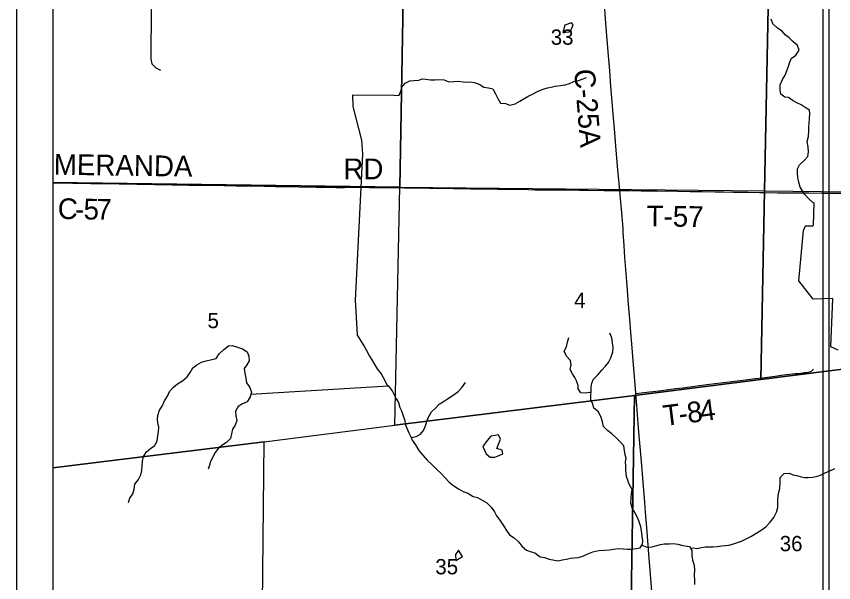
# Model space of a CAD drawing. Extents: x 0 to 1391, y -24 to 440.
# Drawn here: x 490 to 534.79, y 381.91 to 412.96 of the extents above; entities that cross this region are included whole.
import ezdxf

# ---------------------------------------------------------------- set-up
doc = ezdxf.new("R2010")
doc.units = 0
for name, color, linetype in [('GM_X_County_Road', 7, 'Continuous'), ('GM_X_County_Road_Text', 7, 'Continuous'), ('GM_X_Interstate_Route', 7, 'Continuous'), ('GM_X_Minor_Lake', 7, 'Continuous'), ('GM_X_Minor_River', 7, 'Continuous'), ('GM_X_Section', 7, 'Continuous'), ('GM_X_Section_Text', 7, 'Continuous'), ('GM_X_Township', 7, 'Continuous'), ('GM_X_Township_Road', 7, 'Continuous'), ('GM_X_Township_Road_Text', 7, 'Continuous'), ('SH_Data', 7, 'Continuous')]:
    doc.layers.add(name, color=color, linetype=linetype)

msp = doc.modelspace()

# ---------------------------------------------------------------- linework, layer by layer
at = {"layer": 'GM_X_County_Road'}
for points in [[(522.968, 404.52), (522.85, 405.863), (522.775, 406.8), (522.719, 407.384), (522.627, 408.487), (522.583, 409.107), (522.516, 409.987), (522.465, 410.594), (522.354, 411.895), (522.286, 412.812), (522.222, 413.633)], [(523.078, 403.405), (522.983, 404.358), (522.968, 404.52)], [(492, 403.821), (493.098, 403.801), (494.08, 403.789), (495.634, 403.765), (496.603, 403.751), (498.566, 403.719), (499.449, 403.706), (500.17, 403.7), (501.375, 403.677), (502.033, 403.671), (502.605, 403.663), (503.04, 403.657), (503.599, 403.647), (504.208, 403.635), (504.693, 403.631), (505.5, 403.606), (506.444, 403.588), (506.954, 403.585), (507.501, 403.579), (507.973, 403.578), (508.756, 403.581), (509.352, 403.58), (509.937, 403.575), (510.409, 403.569), (511.278, 403.561), (511.925, 403.55), (512.657, 403.536), (513.95, 403.522), (514.546, 403.51), (514.894, 403.504), (515.764, 403.495), (516.373, 403.488), (517.106, 403.481), (517.392, 403.477), (518.063, 403.46), (518.436, 403.45), (520.089, 403.44), (520.859, 403.431), (521.294, 403.426), (522.189, 403.411), (523.078, 403.405)], [(523.26, 401.112), (523.247, 401.319), (523.197, 401.989), (523.114, 402.969), (523.078, 403.405)], [(523.947, 392.283), (523.923, 392.552), (523.821, 393.853), (523.73, 394.993), (523.679, 395.629), (523.639, 396.132), (523.555, 397.173), (523.457, 398.424), (523.349, 399.73), (523.307, 400.388), (523.26, 401.112)], [(525.306, 375.36), (525.265, 375.917), (525.169, 377.156), (524.994, 379.348), (524.898, 380.487), (524.731, 382.594), (524.682, 383.226), (524.546, 384.923), (524.496, 385.53), (524.433, 386.31), (524.345, 387.425), (524.25, 388.552), (524.156, 389.753), (524.084, 390.608), (524.005, 391.636), (523.947, 392.283)]]:
    msp.add_lwpolyline(points, dxfattribs=at)
at = {"layer": 'GM_X_Interstate_Route'}
for points in [[(534.216, 381.071), (534.213, 382.737), (534.211, 383.855), (534.212, 384.936), (534.211, 386.54), (534.212, 388.105), (534.215, 390.206), (534.213, 391.175), (534.214, 392.666), (534.212, 394.307), (534.212, 396.109), (534.209, 397.861), (534.211, 398.321), (534.216, 399.303), (534.216, 400.098), (534.212, 401.142), (534.211, 402.136), (534.215, 403.266), (534.215, 403.4), (534.214, 403.603), (534.218, 404.858), (534.213, 406.598), (534.213, 407.219), (534.218, 408.301), (534.216, 409.444), (534.219, 411.097), (534.219, 412.526), (534.215, 414.39)], [(534.547, 380.674), (534.551, 382.041), (534.55, 383.184), (534.551, 383.495), (534.546, 385.346), (534.546, 386.987), (534.544, 387.472), (534.546, 388.652), (534.548, 389.709), (534.542, 392.02), (534.543, 392.94), (534.544, 394.494), (534.547, 395.91), (534.546, 396.78), (534.544, 397.924), (534.542, 399.067), (534.541, 399.8), (534.539, 400.173), (534.542, 402.273), (534.546, 403.263), (534.547, 403.4), (534.545, 404.784), (534.542, 406.188), (534.546, 406.847), (534.546, 406.959), (534.546, 407.257), (534.546, 407.58), (534.543, 408.4), (534.546, 408.972), (534.547, 409.233), (534.546, 409.755), (534.544, 410.501), (534.542, 411.893), (534.543, 412.551), (534.546, 413.496)]]:
    msp.add_lwpolyline(points, dxfattribs=at)
at = {"layer": 'GM_X_Minor_Lake'}
msp.add_line((514.063, 383.449), (514.087, 383.123), dxfattribs=at)
for points in [[(520.379, 412.172), (520.505, 412.496), (520.423, 412.604), (520.066, 412.473)], [(520.066, 412.473), (519.945, 412.071), (520.272, 412.105), (520.379, 412.172)], [(516.332, 389.263), (516.539, 389.768), (516.422, 390.02), (516.231, 389.971), (515.995, 389.93), (515.793, 389.7), (515.567, 389.379)], [(515.567, 389.379), (515.742, 388.966), (515.974, 388.779), (516.218, 388.782), (516.409, 388.854), (516.654, 388.978), (516.627, 389.168), (516.332, 389.263)], [(514.447, 383.348), (514.234, 383.68), (514.063, 383.449)], [(514.087, 383.123), (514.447, 383.348)]]:
    msp.add_lwpolyline(points, dxfattribs=at)
at = {"layer": 'GM_X_Minor_River'}
msp.add_line((502.85, 392.235), (510.373, 392.692), dxfattribs=at)
for points in [[(497.769, 417.033), (497.745, 414.02), (497.395, 413.403), (497.366, 410.61)], [(533.725, 402.722), (533.65, 402.754), (533.424, 402.946), (533.208, 403.192), (533.074, 403.384), (532.962, 403.582), (532.875, 403.857), (532.818, 404.115), (532.806, 404.351), (532.809, 404.586), (532.925, 404.82), (533.171, 405.044), (533.379, 405.276), (533.405, 405.534), (533.386, 405.8), (533.337, 406.089), (533.409, 406.361), (533.421, 406.687), (533.431, 406.884), (533.441, 407.104), (533.467, 407.354), (533.478, 407.612), (533.466, 407.802), (533.225, 407.949), (533.007, 408.112), (532.773, 408.206), (532.562, 408.315), (532.306, 408.508), (532.117, 408.518), (531.899, 408.688), (531.856, 408.924), (531.852, 409.205), (531.985, 409.484), (532.132, 409.732), (532.227, 409.966), (532.29, 410.17), (532.361, 410.389), (532.463, 410.638), (532.724, 410.832), (532.902, 411.095), (532.814, 411.354), (532.536, 411.586), (532.342, 411.778), (532.139, 411.948), (531.974, 412.14), (531.711, 412.31), (531.464, 412.541), (531.361, 412.808)], [(497.366, 410.61), (497.416, 410.344), (497.648, 410.136), (497.905, 410.012)], [(510.695, 408.608), (510.984, 408.627), (511.07, 408.854), (511.134, 409.081), (511.303, 409.291), (511.563, 409.424), (511.791, 409.444), (512.049, 409.456), (512.24, 409.529), (512.437, 409.504), (512.694, 409.471), (512.937, 409.475), (513.188, 409.487), (513.438, 409.476), (513.695, 409.359), (513.96, 409.379), (514.219, 409.398), (514.484, 409.357), (514.689, 409.354), (514.894, 409.367), (515.09, 409.319), (515.355, 409.232), (515.618, 409.077), (515.868, 409.043), (516.103, 408.972), (516.266, 408.712), (516.377, 408.445), (516.525, 408.2), (516.798, 408.182), (517.047, 408.08), (517.329, 408.167), (517.589, 408.3), (517.857, 408.464), (518.086, 408.597), (518.284, 408.693), (518.529, 408.819), (518.727, 408.908), (518.918, 408.989), (519.116, 409.039), (519.306, 409.075), (519.52, 409.125), (519.816, 409.167), (520.075, 409.209), (520.311, 409.282), (520.555, 409.377), (520.806, 409.442), (521.058, 409.53), (521.248, 409.603)], [(510.695, 408.608), (508.426, 408.629), (508.441, 408.021), (508.918, 406.164), (508.968, 405.397), (508.56, 397.389), (508.679, 395.51)], [(534.643, 394.845), (534.749, 397.48), (533.664, 397.457), (532.872, 398.454), (533.136, 401.205), (533.238, 401.462), (533.625, 401.464), (533.679, 401.509), (533.725, 402.714)], [(510.413, 392.657), (510.315, 392.742), (510.227, 392.932), (510.123, 393.139), (509.989, 393.376), (509.794, 393.621), (509.623, 393.904), (509.504, 394.125), (509.333, 394.386), (509.184, 394.653), (509.058, 394.898), (508.679, 395.51)], [(522.625, 395.328), (522.515, 395.58)], [(511.64, 389.865), (511.684, 389.72), (511.87, 389.46), (512.064, 389.153), (512.266, 388.908), (512.521, 388.631), (512.769, 388.385), (513.047, 388.108), (513.257, 387.915), (513.505, 387.661), (513.723, 387.415), (513.971, 387.214), (514.228, 387.051), (514.484, 386.903), (514.749, 386.808), (515.028, 386.63), (515.271, 386.58), (515.528, 386.425), (515.777, 386.277), (516.017, 386.053), (516.204, 385.793), (516.315, 385.571), (516.503, 385.341), (516.674, 385.066), (516.815, 384.813), (517.032, 384.522), (517.281, 384.359), (517.522, 384.143), (517.716, 383.897), (517.964, 383.689), (518.161, 383.61), (518.419, 383.538), (518.698, 383.329), (518.94, 383.279), (519.19, 383.192), (519.684, 383.108), (519.912, 383.15), (520.156, 383.192), (520.37, 383.241), (520.56, 383.261), (520.781, 383.295), (521.041, 383.359), (521.316, 383.491), (521.584, 383.593), (521.919, 383.664), (522.239, 383.689), (522.506, 383.707), (522.727, 383.734), (522.986, 383.775), (523.259, 383.763), (523.495, 383.744), (523.708, 383.741), (523.982, 383.774), (524.188, 383.824), (524.32, 384.026), (524.323, 384.216), (524.295, 384.451), (524.254, 384.763), (524.226, 384.975), (524.123, 385.25), (524.065, 385.448), (523.916, 385.723), (523.752, 386.006), (523.68, 386.28), (523.691, 386.545), (523.717, 386.794), (523.743, 387.021), (523.572, 387.335), (523.513, 387.525), (523.44, 387.723), (523.399, 388.057), (523.394, 388.307), (523.382, 388.527), (523.415, 388.724), (523.364, 388.914), (523.322, 389.157), (523.287, 389.408), (523.069, 389.654), (522.844, 389.869), (522.633, 390.062), (522.4, 390.255), (522.182, 390.471), (522.125, 390.715), (522.052, 390.958), (521.896, 391.264), (521.655, 391.48), (521.59, 391.716), (521.486, 391.907), (521.474, 392.165), (521.508, 392.429), (521.503, 392.619), (521.544, 392.853), (521.63, 393.056), (521.869, 393.295), (522.078, 393.557), (522.294, 393.78), (522.456, 393.982), (522.581, 394.23), (522.692, 394.562), (522.71, 394.797), (522.625, 395.328)], [(521.499, 392.364), (521.423, 392.325), (521.187, 392.29), (520.928, 392.317), (520.779, 392.532), (520.781, 392.721), (520.701, 392.965), (520.604, 393.156), (520.478, 393.347), (520.344, 393.592), (520.4, 393.841), (520.366, 394.092), (520.14, 394.33), (520.022, 394.597), (520.155, 394.838), (520.211, 395.094), (520.268, 395.351)], [(496.153, 386.299), (496.225, 386.533), (496.38, 386.773), (496.46, 387.03), (496.486, 387.302), (496.695, 387.556), (496.82, 387.812), (496.868, 388.061), (496.887, 388.311), (496.913, 388.568), (496.977, 388.825), (497.14, 389.087), (497.379, 389.273), (497.57, 389.414), (497.726, 389.669), (497.76, 389.979), (497.793, 390.183), (497.812, 390.433), (497.754, 390.661), (497.734, 390.874), (497.759, 391.07), (497.839, 391.365), (497.986, 391.582), (498.112, 391.883), (498.275, 392.123), (498.4, 392.379), (498.608, 392.633), (498.839, 392.804), (499.107, 392.966), (499.353, 393.182), (499.531, 393.422), (499.672, 393.677), (499.894, 393.856), (500.147, 393.996), (500.407, 394.075), (500.704, 394.139), (500.949, 394.203), (501.112, 394.458), (501.366, 394.689), (501.627, 394.89), (501.832, 394.902), (502.113, 394.822), (502.401, 394.727), (502.657, 394.556), (502.738, 394.327), (502.765, 394.069), (502.633, 393.844), (502.478, 393.649), (502.513, 393.391), (502.57, 393.125), (502.62, 392.859), (502.791, 392.599), (502.887, 392.355), (502.808, 392.099), (502.652, 391.828), (502.392, 391.704), (502.154, 391.571), (502.014, 391.315), (502.034, 391.057), (502.091, 390.791), (501.997, 390.55), (501.842, 390.325), (501.785, 390.069), (501.744, 389.804), (501.52, 389.595), (501.321, 389.455), (501.067, 389.254), (500.858, 388.984), (500.749, 388.751), (500.64, 388.548), (500.584, 388.352), (500.513, 388.133)], [(535.031, 394.649), (534.643, 394.845)], [(510.413, 392.657), (510.6, 392.427), (510.696, 392.198), (510.808, 391.984), (510.934, 391.777), (511.022, 391.511), (511.103, 391.32), (511.199, 391.053), (511.272, 390.848), (511.322, 390.559), (511.403, 390.368), (511.514, 390.117), (511.64, 389.865), (511.907, 389.914), (512.144, 390.046), (512.307, 390.256), (512.416, 390.512), (512.488, 390.768), (512.613, 391.024), (512.753, 391.279), (512.946, 391.451), (513.169, 391.69), (513.415, 391.845), (513.629, 391.978), (513.929, 392.186), (514.205, 392.393), (514.436, 392.625), (514.622, 392.887)], [(526.939, 383.805), (527.094, 383.815), (527.291, 383.781), (527.543, 383.83), (527.756, 383.872), (527.969, 383.876), (528.182, 383.873), (528.411, 383.884), (528.662, 383.918), (528.853, 383.938), (529.051, 383.965), (529.249, 384.022), (529.524, 384.109), (529.73, 384.181), (529.991, 384.306), (530.259, 384.445), (530.573, 384.645), (530.818, 384.785), (531.079, 384.97), (531.311, 385.224), (531.512, 385.486), (531.66, 385.771), (531.724, 386.028), (531.728, 386.27), (531.738, 386.467), (531.772, 386.792), (531.844, 387.072), (531.849, 387.412), (531.86, 387.67), (532.083, 387.893), (532.342, 387.904), (532.554, 387.825), (532.766, 387.776), (533.001, 387.704), (533.206, 387.671), (533.396, 387.667), (533.64, 387.694), (533.831, 387.721), (534.075, 387.808), (534.328, 387.933), (534.588, 388.042), (534.848, 388.159)], [(524.282, 383.969), (524.554, 383.856), (524.835, 383.874), (525.095, 383.946), (525.293, 383.996), (525.492, 384.03), (525.796, 384.041), (525.986, 384.045), (526.244, 384.018), (526.449, 383.969), (526.639, 383.921), (526.897, 383.886), (527.008, 383.672), (527.02, 383.399), (527.055, 383.134), (527.142, 382.859), (527.162, 382.586), (527.151, 382.321), (527.162, 382.048), (527.167, 381.798)]]:
    msp.add_lwpolyline(points, dxfattribs=at)
at = {"layer": 'GM_X_Section'}
for p, q in [((492, 403.851), (492, 388.207)), ((492, 388.207), (492, 375.413))]:
    msp.add_line(p, q, dxfattribs=at)
for points in [[(511.262, 418), (492, 418), (492, 403.851)], [(492, 403.851), (511.009, 403.582), (511.262, 418)], [(511.262, 418), (511.009, 403.582), (531.004, 403.382), (531.299, 418)], [(531.299, 418), (531.004, 403.382), (551.127, 403.143), (551.455, 418)], [(492, 388.207), (503.573, 389.632), (510.734, 390.543), (511.009, 403.582), (492, 403.851)], [(492, 375.413), (503.435, 375.392), (503.573, 389.632), (492, 388.207)]]:
    msp.add_lwpolyline(points, dxfattribs=at)
for points in [[(511.009, 403.582), (531.004, 403.382), (530.802, 393.045), (523.87, 392.175), (510.734, 390.543)], [(531.004, 403.382), (551.127, 403.143), (550.964, 395.616), (548.844, 395.312), (543.962, 394.707), (530.802, 393.045)], [(530.802, 393.045), (543.962, 394.707), (543.747, 375.22), (523.606, 375.279), (523.87, 392.175)], [(523.87, 392.175), (523.606, 375.279), (503.957, 375.36), (503.435, 375.392), (503.573, 389.632), (510.734, 390.543)]]:
    msp.add_lwpolyline(points, close=True, dxfattribs=at)
at = {"layer": 'GM_X_Township'}
msp.add_lwpolyline([(563.833, 373.178), (563.849, 374.981), (563.918, 383.057), (564.071, 397.264), (576.025, 398.776), (588.961, 400.394), (591.398, 400.66), (591.42, 402.56), (591.526, 412.457), (591.623, 418), (492, 418), (492, 315.227)], dxfattribs=at)
at = {"layer": 'GM_X_Township_Road'}
for points in [[(523.078, 403.405), (523.616, 403.398), (524.237, 403.391), (525.033, 403.396), (525.12, 403.396), (526.21, 403.377), (526.918, 403.36), (527.589, 403.352), (528.297, 403.339), (528.744, 403.328), (529.303, 403.321), (530.111, 403.309), (530.732, 403.299), (530.959, 403.296)], [(530.959, 403.296), (531.726, 403.288), (532.186, 403.283), (532.683, 403.284), (533.428, 403.275), (534.215, 403.266), (534.546, 403.263), (535.23, 403.258), (535.801, 403.25), (536.434, 403.238), (536.944, 403.234), (537.28, 403.231)], [(523.947, 392.283), (524.105, 392.297), (524.24, 392.309), (524.696, 392.364), (525.226, 392.43), (526.113, 392.543), (526.532, 392.597), (527.838, 392.762), (528.294, 392.818), (529.81, 393.007), (530.5, 393.094), (530.882, 393.141), (531.584, 393.23), (531.917, 393.274), (532.682, 393.366), (532.806, 393.381), (533.115, 393.418), (533.171, 393.425)], [(533.171, 393.425), (533.275, 393.437), (533.372, 393.452), (533.444, 393.467), (533.537, 393.491), (533.569, 393.504), (533.606, 393.53), (533.631, 393.552), (533.656, 393.581), (533.679, 393.609)]]:
    msp.add_lwpolyline(points, dxfattribs=at)
at = {"layer": 'SH_Data'}
for p, q in [((490, 420), (490, 280)), ((492, 418), (492, 282)), ((492, 418), (492, 282))]:
    msp.add_line(p, q, dxfattribs=at)

# ---------------------------------------------------------------- texts
at = {"layer": 'GM_X_County_Road_Text'}
for s, height, rotation, p in [('C-25A', 1.1364, 274.6967, (520.561, 410.028)), ('MERANDA', 1.1364, 359.1895, (492.045, 404.273)), ('RD', 1.1364, 0, (507.919, 404.023)), ('C', 1.136, 358.134, (492.253, 401.857)), ('5', 1.136, 359.4144, (493.68, 401.819)), ('7', 1.136, 359.5213, (494.382, 401.812)), ('-', 1.136, 359.0699, (493.206, 401.826))]:
    msp.add_text(s, height=height, rotation=rotation, dxfattribs=at).set_placement(p)
at = {"layer": 'GM_X_Section_Text'}
for s, height, p in [('33', 0.8371, (519.286, 411.398)), ('4', 0.837, (520.569, 396.971)), ('5', 0.837, (500.477, 395.858)), ('36', 0.8371, (531.835, 383.631)), ('35', 0.8371, (512.961, 382.364))]:
    msp.add_text(s, height=height, rotation=0, dxfattribs=at).set_placement(p)
at = {"layer": 'GM_X_Township_Road_Text'}
for s, height, rotation, p in [('T-57', 1.1364, 359.3037, (524.532, 401.443)), ('4', 1.136, 7.8926, (527.53, 390.741)), ('T', 1.136, 7.0373, (525.51, 390.489)), ('8', 1.136, 7.215, (526.821, 390.651)), ('-', 1.136, 7.0692, (526.355, 390.593))]:
    msp.add_text(s, height=height, rotation=rotation, dxfattribs=at).set_placement(p)

doc.saveas('drawing.dxf')
